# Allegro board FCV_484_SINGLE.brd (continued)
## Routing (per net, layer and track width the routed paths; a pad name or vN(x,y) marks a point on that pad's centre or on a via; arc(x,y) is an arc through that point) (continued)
IO-BANK4_18: length 1.2
  TOP w0.127: U1.L1 164.39,168.57
IO-BANK4_19: length 2.2
  TOP w0.127: 164.39,168.97 165.99,168.97 U1.L2
IO-BANK4_20: length 2.8
  TOP w0.127: U1.L3 v1(166.79,168.97)
  SIG1 w0.127: v1(166.79,168.97) 164.52,168.97
IO-BANK4_21: length 5.1
  TOP w0.127: U1.L5 v1(168.39,168.97)
  SIG1 w0.127: v1(168.39,168.97) 167.97,168.55 166.04,168.55 165.89,168.71 164.13,168.71
IO-BANK4_22: length 6
  TOP w0.127: U1.L6 v1(169.19,168.97)
  SIG1 w0.127: 164.13,168.43 165.76,168.43 165.89,168.3 168.52,168.3 v1(169.19,168.97)
IO-BANK4_23: length 5.6
  TOP w0.127: U1.L7 v1(169.99,168.97)
  SIG2 w0.127: v1(169.99,168.97) 169.34,168.33 165.25,168.33
IO-BANK4_24: length 7.4
  TOP w0.127: U1.L8 v1(170.79,168.97)
  SIG3 w0.127: v1(170.79,168.97) 170.4,168.58 166.41,168.58 165.95,169.04 164.34,169.04
IO-BANK4_25: length 2.2
  TOP w0.127: 164.39,168.2 165.35,168.2 165.38,168.17 165.99,168.17 U1.M2
IO-BANK4_26: length 3.3
  TOP w0.127: U1.M3 v1(166.79,167.37)
  SIG1 w0.127: v1(166.79,167.37) 165.87,167.37 165.49,166.99 164.25,166.99
IO-BANK4_27: length 4.3
  TOP w0.127: U1.M4 v1(167.59,167.37)
  SIG1 w0.127: 164.26,167.31 165.3,167.31 165.79,167.79 167.17,167.79 v1(167.59,167.37)
IO-BANK4_28: length 5.1
  TOP w0.127: U1.M5 v1(168.39,167.37)
  SIG1 w0.127: v1(168.39,167.37) 167.72,168.05 165.66,168.05 165.54,168.17 164.21,168.17
IO-BANK4_29: length 5.1
  TOP w0.127: U1.M7 v1(169.99,167.37)
  SIG2 w0.127: v1(169.99,167.37) 169.6,167.77 165.61,167.77
IO-BANK4_30: length 7.4
  TOP w0.127: U1.M8 v1(170.79,167.37)
  SIG3 w0.127: v1(170.79,167.37) 170.4,167.77 165.96,167.77 165.48,167.28 164.31,167.28
IO-BANK4_31: length 8.1
  TOP w0.127: U1.M9 v1(171.59,167.37)
  SIG3 w0.127: 164.44,168.35 165.79,168.35 166.09,168.05 170.92,168.05 v1(171.59,167.37)
IO-BANK4_32: length 1.2
  TOP w0.127: U1.N1 164.39,166.97
IO-BANK4_33: length 2.2
  TOP w0.127: 164.39,167.38 165.98,167.38 U1.N2
IO-BANK4_34: length 4.3
  TOP w0.127: U1.N4 v1(167.59,166.57)
  SIG1 w0.127: 164.21,166.65 165.63,166.65 165.96,166.98 167.18,166.98 v1(167.59,166.57)
IO-BANK4_35: length 3.4
  TOP w0.127: U1.N5 v1(168.39,166.57)
  SIG2 w0.127: 165.76,166.98 167.98,166.98 v1(168.39,166.57)
IO-BANK4_36: length 5.6
  TOP w0.127: U1.N6 v1(169.19,166.57)
  SIG3 w0.127: 164.31,166.97 168.8,166.97 v1(169.19,166.57)
IO-BANK4_37: length 5.4
  TOP w0.127: U1.N7 v1(169.99,166.57)
  SIG2 w0.127: v1(169.99,166.57) 169.58,166.17 165.33,166.17
IO-BANK4_38: length 6.9
  TOP w0.127: U1.N8 v1(170.79,166.57)
  SIG2 w0.127: v1(170.79,166.57) 170.4,166.97 170.4,167.75 170.13,168.02 165.56,168.02
IO-BANK4_39: length 1.2
  TOP w0.127: U1.P1 164.39,166.17
IO-BANK4_40: length 2.2
  TOP w0.127: U1.P2 165.99,166.58 164.39,166.58
IO-BANK4_41: length 3.2
  TOP w0.127: U1.P3 v1(166.79,165.77)
  SIG1 w0.127: v1(166.79,165.77) 164.15,165.77
IO-BANK4_42: length 4.2
  TOP w0.127: U1.P4 v1(167.59,165.77)
  SIG1 w0.127: v1(167.59,165.77) 167.18,166.18 164.15,166.18
IO-BANK4_43: length 5.4
  TOP w0.127: U1.P6 v1(169.19,165.77)
  SIG3 w0.127: v1(169.19,165.77) 168.8,165.38 164.54,165.38
IO-BANK4_44: length 6.2
  TOP w0.127: U1.P7 v1(169.99,165.77)
  SIG3 w0.127: v1(169.99,165.77) 169.6,166.17 164.54,166.17
IO-BANK4_45: length 7.3
  TOP w0.127: U1.P8 v1(170.79,165.77)
  SIG3 w0.127: v1(170.79,165.77) 170.4,165.38 169.77,165.38 169.6,165.2 169.6,159.92
IO-BANK4_46: length 7.3
  TOP w0.127: U1.P9 v1(171.59,165.77)
  SIG3 w0.127: 172,159.26 172,165.37 v1(171.59,165.77)
IO-BANK4_47: length 1.2
  TOP w0.127: U1.R1 164.39,165.37
IO-BANK4_48: length 3.5
  TOP w0.127: U1.R3 v1(166.79,164.97)
  SIG1 w0.127: v1(166.79,164.97) 166.38,164.57 165.7,164.57 165.24,165.02 164.25,165.02
IO-BANK4_49: length 4.2
  TOP w0.127: U1.R4 v1(167.59,164.97)
  SIG1 w0.127: v1(167.59,164.97) 167.2,165.37 164.15,165.37
IO-BANK4_50: length 3.4
  TOP w0.127: U1.R5 v1(168.39,164.97)
  SIG2 w0.127: 165.7,165.37 168,165.37 v1(168.39,164.97)
IO-BANK4_51: length 5.4
  TOP w0.127: U1.R6 v1(169.19,164.97)
  SIG3 w0.127: v1(169.19,164.97) 168.8,164.58 164.54,164.58
IO-BANK4_52: length 6.2
  TOP w0.127: U1.R8 v1(170.79,164.97)
  SIG3 w0.127: v1(170.79,164.97) 171.2,164.57 171.2,159.54
IO-BANK4_53: length 1.2
  TOP w0.127: U1.T1 164.39,164.57
IO-BANK4_54: length 2.3
  TOP w0.127: U1.T2 166,164.18 164.3,164.18
IO-BANK4_55: length 3.3
  TOP w0.127: U1.T3 v1(166.79,164.17)
  SIG1 w0.127: 164.25,164.63 165.07,164.63 165.53,164.17 v1(166.79,164.17)
IO-BANK4_56: length 3.5
  TOP w0.127: U1.T5 v1(168.39,164.17)
  SIG2 w0.127: 165.66,164.57 168,164.57 v1(168.39,164.17)
IO-BANK5_1: length 1.2
  TOP w0.127: U1.D1 164.39,174.17
IO-BANK5_2: length 2.2
  TOP w0.127: 164.39,174.57 165.99,174.57 U1.D2
IO-BANK5_3: length 1.2
  TOP w0.127: U1.E1 164.39,173.37
IO-BANK5_4: length 2.9
  TOP w0.127: U1.E3 v1(166.79,173.77)
  SIG1 w0.127: v1(166.79,173.77) 166.34,174.22 164.62,174.22
IO-BANK5_5: length 1.2
  TOP w0.127: U1.F1 164.39,172.57
IO-BANK5_6: length 2.2
  TOP w0.127: 164.39,172.97 165.99,172.97 U1.F2
IO-BANK5_7: length 3
  TOP w0.127: U1.F3 v1(166.79,172.97)
  SIG1 w0.127: v1(166.79,172.97) 164.38,172.97
IO-BANK5_8: length 3.8
  TOP w0.127: U1.F5 v1(168.39,172.97)
  SIG2 w0.127: v1(168.39,172.97) 167.98,173.38 165.3,173.38
IO-BANK5_9: length 2.2
  TOP w0.127: 164.39,172.17 165.99,172.17 U1.G2
IO-BANK5_10: length 3
  TOP w0.127: U1.G3 v1(166.79,172.17)
  SIG1 w0.127: v1(166.79,172.17) 164.38,172.17
IO-BANK5_11: length 4
  TOP w0.127: U1.G4 v1(167.59,172.17)
  SIG1 w0.127: 164.52,171.3 165.74,171.3 166.22,171.78 167.2,171.78 v1(167.59,172.17)
IO-BANK5_12: length 4.7
  TOP w0.127: U1.G5 v1(168.39,172.17)
  SIG1 w0.127: v1(168.39,172.17) 168,172.57 164.38,172.57
JTAG-IO_1: length 5.4
  TOP w0.127: U1.F6 v1(169.19,172.97)
  SIG3 w0.127: 164.52,172.58 168.8,172.58 v1(169.19,172.97)
JTAG-IO_2: length 4.5
  TOP w0.127: U1.F7 v1(169.99,172.97)
  SIG2 w0.127: v1(169.99,172.97) 169.6,173.37 169.6,176.76
JTAG-IO_3: length 4.4
  TOP w0.127: U1.F8 v1(170.79,172.97)
  SIG1 w0.127: 170.4,176.64 170.4,173.37 v1(170.79,172.97)
JTAG-IO_4: length 5.4
  TOP w0.127: U1.G7 v1(169.99,172.17)
  SIG3 w0.127: 169.6,176.81 169.6,172.57 v1(169.99,172.17)
JTAG-IO_5: length 7
  TOP w0.127: U1.G8 v1(170.79,172.17)
  SIG2 w0.127: 164.54,172.57 170.4,172.57 v1(170.79,172.17)
JTAG-IO_6: length 5.4
  TOP w0.127: U1.G9 v1(171.59,172.17)
  SIG3 w0.127: 171.2,176.89 171.2,172.57 v1(171.59,172.17)
JTAG-IO_7: length 5.3
  TOP w0.127: U1.G10 v1(172.39,172.17)
  SIG3 w0.127: v1(172.39,172.17) 172.8,172.58 172.8,176.76
JTAG-IO_8: length 3.8
  TOP w0.127: U1.H4 v1(167.59,171.37)
  SIG1 w0.127: 164.57,170.97 167.18,170.97 v1(167.59,171.37)
JTAG-IO_9: length 3.4
  TOP w0.127: U1.H5 v1(168.39,171.37)
  SIG2 w0.127: v1(168.39,171.37) 168,171.77 165.74,171.77
JTAG-IO_10: length 5.7
  TOP w0.127: U1.H6 v1(169.19,171.37)
  SIG3 w0.127: v1(169.19,171.37) 168.8,170.98 164.24,170.98
JTAG-IO_11: length 6.4
  TOP w0.127: U1.H7 v1(169.99,171.37)
  SIG3 w0.127: 164.49,172.24 165.25,172.24 165.71,171.78 169.58,171.78 v1(169.99,171.37)
JTAG-IO_12: length 6.2
  TOP w0.127: U1.H9 v1(171.59,171.37)
  SIG3 w0.127: v1(171.59,171.37) 171.98,171.77 171.98,176.81
JTAG-IO_13: length 6.8
  TOP w0.127: U1.H10 v1(172.39,171.37)
  SIG3 w0.127: 173.69,176.73 173.69,172.11 173.36,171.78 172.8,171.78 v1(172.39,171.37)
REFCLK0_1: length 2.9
  TOP w0.127: U1.N19 v1(180.39,166.57)
  SIG1 w0.127: v1(180.39,166.57) 180.8,166.98 182.52,166.98
REFCLK0_2: length 2.1
  TOP w0.127: U1.N20 v1(181.19,166.57)
  SIG1 w0.127: 182.52,166.14 181.62,166.14 v1(181.19,166.57)
REFCLK1_1: length 2.8
  TOP w0.127: U1.L19 v1(180.39,168.97)
  SIG1 w0.127: 182.4,168.45 180.91,168.45 v1(180.39,168.97)
REFCLK1_2: length 2
  TOP w0.127: U1.L20 v1(181.19,168.97)
  SIG1 w0.127: 182.45,169.39 181.61,169.39 v1(181.19,168.97)
REFCLK2_1: length 2.8
  TOP w0.127: U1.J19 v1(180.39,170.57)
  SIG1 w0.127: 182.47,170.97 180.78,170.97 v1(180.39,170.57)
REFCLK2_2: length 2
  TOP w0.127: U1.J20 v1(181.19,170.57)
  SIG1 w0.127: v1(181.19,170.57) 181.69,170.08 182.45,170.08
RX0_1: length 2.8
  TOP w0.127: U1.R19 v1(180.39,164.97)
  SIG1 w0.127: v1(180.39,164.97) 180.8,165.38 182.42,165.38
RX0_2: length 2.2
  TOP w0.127: U1.R20 v1(181.19,164.97)
  SIG1 w0.127: v1(181.19,164.97) 181.65,164.52 182.6,164.52
RX1_1: length 2.1
  TOP w0.127: 183.54,167.38 181.98,167.38 U1.M21
RX1_2: length 1.1
  TOP w0.127: U1.M22 183.48,167.77
RX2_1: length 2.3
  TOP w0.127: 183.69,169.77 181.99,169.77 U1.K21
RX2_2: length 1.3
  TOP w0.127: U1.K22 183.7,169.37
RX3_1: length 3.3
  TOP w0.127: U1.G19 v1(180.39,172.17)
  SIG2 w0.127: 182.93,172.58 180.8,172.58 v1(180.39,172.17)
RX3_2: length 2.1
  TOP w0.127: U1.G20 v1(181.19,172.17)
  SIG1 w0.127: v1(181.19,172.17) 181.61,172.59 182.55,172.59
SERDES_VREF: length 1.1
  TOP w0.381: U1.H18 v1(179.59,171.37) ; U1.H19 v1(180.39,171.37)
TX0_1: length 2.1
  TOP w0.127: 183.57,164.18 181.98,164.18 U1.T21
TX0_2: length 1.1
  TOP w0.127: U1.T22 183.48,164.57
TX1_1: length 2.2
  TOP w0.127: U1.P21 181.98,165.78 183.64,165.78
TX1_2: length 1.1
  TOP w0.127: U1.P22 183.51,166.17
TX2_1: length 2.2
  TOP w0.127: U1.H21 181.98,171.36 183.64,171.36
TX2_2: length 1.3
  TOP w0.127: U1.H22 183.7,170.97
TX3_1: length 2.3
  TOP w0.127: 183.77,172.97 181.99,172.97 U1.F21
TX3_2: length 1.4
  TOP w0.127: U1.F22 183.8,172.57
